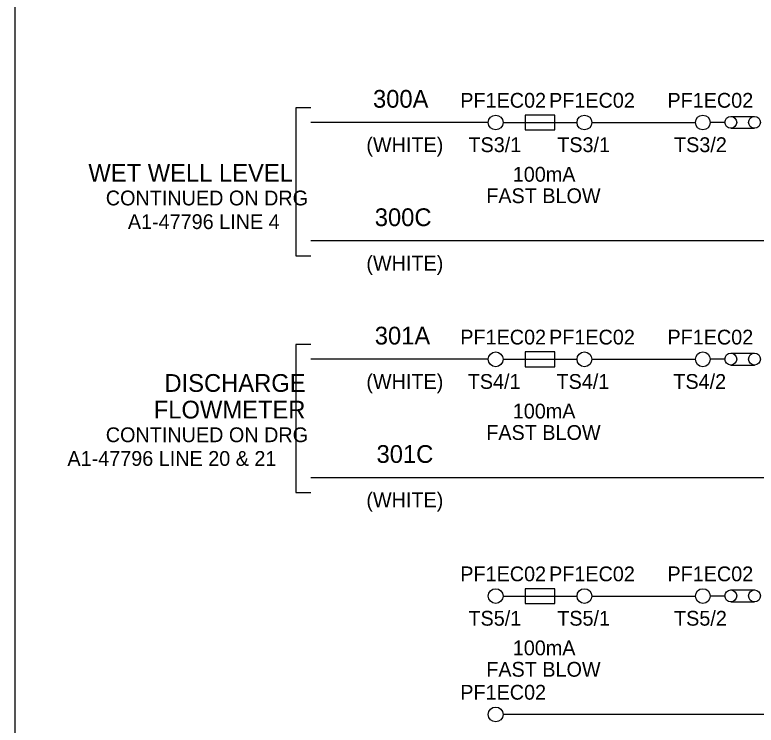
# Model space of a CAD drawing. Extents: x 0 to 841, y 0 to 594.
# Drawn here: x 550 to 675.3, y 138.2 to 258.2 of the extents above; entities that cross this region are included whole.
import ezdxf

# ---------------------------------------------------------------- set-up
doc = ezdxf.new("R2010")
doc.units = 0
doc.layers.add('Level 1', color=7, linetype='Continuous')
doc.layers.add('Level 10', color=7, linetype='Continuous')

msp = doc.modelspace()

# ---------------------------------------------------------------- linework, layer by layer
at = {"layer": 'Level 1'}
for p, q in [((550, 572.5), (550, 57)), ((670.98, 241.03), (674.98, 241.03)), ((630, 240), (600, 240)), ((632.5, 240), (645, 240)), ((647.5, 240), (665, 240)), ((670, 240), (667.5, 240)), ((670.98, 239.03), (674.98, 239.03)), ((680, 220), (600, 220)), ((670.98, 201.03), (674.98, 201.03)), ((630, 200), (600, 200)), ((632.5, 200), (645, 200)), ((647.5, 200), (665, 200)), ((670, 200), (667.5, 200)), ((670.98, 199.03), (674.98, 199.03)), ((680, 180), (600, 180)), ((670.98, 161.03), (674.98, 161.03)), ((632.5, 160), (645, 160)), ((647.5, 160), (665, 160)), ((670, 160), (667.5, 160)), ((670.98, 159.03), (674.98, 159.03)), ((680, 140), (632.5, 140))]:
    msp.add_line(p, q, dxfattribs=at)
for points in [[(600, 242.5), (597.5, 242.5), (597.5, 217.5), (600, 217.5)], [(600, 202.5), (597.5, 202.5), (597.5, 177.5), (600, 177.5)]]:
    msp.add_lwpolyline(points, dxfattribs=at)
for points in [[(636.25, 238.75), (641.25, 238.75), (641.25, 241.25), (636.25, 241.25)], [(636.25, 198.75), (641.25, 198.75), (641.25, 201.25), (636.25, 201.25)], [(636.25, 158.75), (641.25, 158.75), (641.25, 161.25), (636.25, 161.25)]]:
    msp.add_lwpolyline(points, close=True, dxfattribs=at)
for centre in [(670.98, 240.03), (674.98, 240.03), (670.98, 200.03), (674.98, 200.03), (670.98, 160.03), (674.98, 160.03)]:
    msp.add_circle(centre, 1, dxfattribs=at)
at = {"layer": 'Level 10'}
for centre in [(631.25, 240), (646.25, 240), (666.25, 240), (631.25, 200), (646.25, 200), (666.25, 200), (631.25, 160), (646.25, 160), (666.25, 160), (631.25, 140)]:
    msp.add_circle(centre, 1.25, dxfattribs=at)

# ---------------------------------------------------------------- texts
at = {"layer": 'Level 1'}
for s, height, p in [('300A', 3, (610.52, 242.5)), ('PF1EC02', 2.5, (625.27, 242.5)), ('PF1EC02', 2.5, (640.27, 242.5)), ('PF1EC02', 2.5, (660.27, 242.5)), ('(WHITE)', 2.5, (609.4, 235)), ('TS3/1', 2.5, (626.65, 235)), ('TS3/1', 2.5, (641.65, 235)), ('TS3/2', 2.5, (661.39, 235)), ('WET WELL LEVEL', 3, (562.43, 230)), ('100mA', 2.5, (634.14, 230)), ('CONTINUED ON DRG', 2.5, (565.37, 226)), ('FAST BLOW', 2.5, (629.66, 226.38)), ('300C', 3, (610.82, 222.5)), ('A1-47796 LINE 4', 2.5, (569.1, 222)), ('(WHITE)', 2.5, (609.4, 215)), ('301A', 3, (610.82, 202.5)), ('PF1EC02', 2.5, (625.27, 202.5)), ('PF1EC02', 2.5, (640.27, 202.5)), ('PF1EC02', 2.5, (660.27, 202.5)), ('DISCHARGE', 3, (575.28, 194.5)), ('(WHITE)', 2.5, (609.4, 195)), ('TS4/1', 2.5, (626.53, 195)), ('TS4/1', 2.5, (641.53, 195)), ('TS4/2', 2.5, (661.27, 195)), ('FLOWMETER', 3, (573.48, 190)), ('100mA', 2.5, (634.14, 190)), ('CONTINUED ON DRG', 2.5, (565.37, 186)), ('FAST BLOW', 2.5, (629.66, 186.38)), ('301C', 3, (611.12, 182.5)), ('A1-47796 LINE 20 & 21', 2.5, (558.89, 182)), ('(WHITE)', 2.5, (609.4, 175)), ('PF1EC02', 2.5, (625.27, 162.5)), ('PF1EC02', 2.5, (640.27, 162.5)), ('PF1EC02', 2.5, (660.27, 162.5)), ('TS5/1', 2.5, (626.65, 155)), ('TS5/1', 2.5, (641.65, 155)), ('TS5/2', 2.5, (661.39, 155)), ('100mA', 2.5, (634.14, 150)), ('FAST BLOW', 2.5, (629.66, 146.38)), ('PF1EC02', 2.5, (625.27, 142.5))]:
    msp.add_text(s, height=height, dxfattribs=at).set_placement(p)

doc.saveas('drawing.dxf')
